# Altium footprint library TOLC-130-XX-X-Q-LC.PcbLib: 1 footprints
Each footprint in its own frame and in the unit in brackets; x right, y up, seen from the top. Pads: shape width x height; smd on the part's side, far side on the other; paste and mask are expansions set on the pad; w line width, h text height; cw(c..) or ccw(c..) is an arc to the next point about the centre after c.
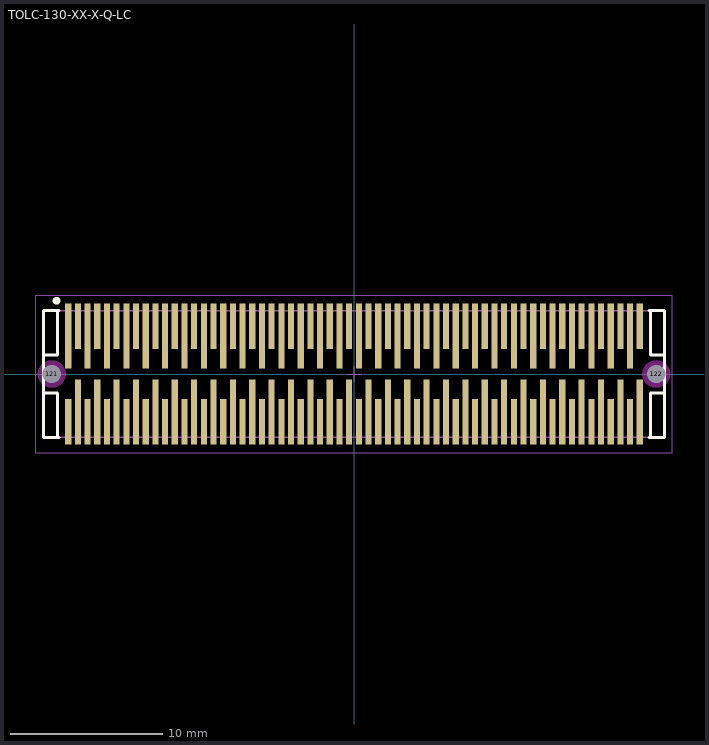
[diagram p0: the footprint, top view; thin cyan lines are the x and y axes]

## TOLC-130-XX-X-Q-LC [mm] "1.27mm pitch, 120 pin, terminal strip; 4 rows, w/locking clips, SMT"
height 5.59
pads (122):
  rect 0.4x4.25 smd mask+0: 1(-18.732,2.5) 4(-18.098,-2.5) 5(-17.462,2.5) 8(-16.828,-2.5) 9(-16.192,2.5) 12(-15.557,-2.5) 13(-14.922,2.5) 16(-14.287,-2.5) 17(-13.652,2.5) 20(-13.018,-2.5) 21(-12.383,2.5) 24(-11.747,-2.5) 25(-11.112,2.5) 28(-10.477,-2.5) 29(-9.842,2.5) 32(-9.207,-2.5) 33(-8.572,2.5) 36(-7.938,-2.5) 37(-7.302,2.5) 40(-6.667,-2.5) 41(-6.032,2.5) 44(-5.397,-2.5) 45(-4.763,2.5) 48(-4.127,-2.5) 49(-3.492,2.5) 52(-2.857,-2.5) 53(-2.222,2.5) 56(-1.587,-2.5) 57(-0.953,2.5) 60(-0.318,-2.5) 61(0.318,2.5) 64(0.953,-2.5) 65(1.587,2.5) 68(2.222,-2.5) 69(2.857,2.5) 72(3.492,-2.5) 73(4.127,2.5) 76(4.763,-2.5) 77(5.397,2.5) 80(6.032,-2.5) 81(6.667,2.5) 84(7.302,-2.5) 85(7.938,2.5) 88(8.572,-2.5) 89(9.207,2.5) 92(9.842,-2.5) 93(10.477,2.5) 96(11.112,-2.5) 97(11.747,2.5) 100(12.383,-2.5) 101(13.018,2.5) 104(13.652,-2.5) 105(14.287,2.5) 108(14.922,-2.5) 109(15.557,2.5) 112(16.192,-2.5) 113(16.828,2.5) 116(17.462,-2.5) 117(18.098,2.5) 120(18.732,-2.5)
  rect 0.4x3 smd mask+0: 2(-18.732,-3.135) 3(-18.098,3.135) 6(-17.462,-3.135) 7(-16.828,3.135) 10(-16.192,-3.135) 11(-15.557,3.135) 14(-14.922,-3.135) 15(-14.287,3.135) 18(-13.652,-3.135) 19(-13.018,3.135) 22(-12.383,-3.135) 23(-11.747,3.135) 26(-11.112,-3.135) 27(-10.477,3.135) 30(-9.842,-3.135) 31(-9.207,3.135) 34(-8.572,-3.135) 35(-7.938,3.135) 38(-7.302,-3.135) 39(-6.667,3.135) 42(-6.032,-3.135) 43(-5.397,3.135) 46(-4.763,-3.135) 47(-4.127,3.135) 50(-3.492,-3.135) 51(-2.857,3.135) 54(-2.222,-3.135) 55(-1.587,3.135) 58(-0.953,-3.135) 59(-0.318,3.135) 62(0.318,-3.135) 63(0.953,3.135) 66(1.587,-3.135) 67(2.222,3.135) 70(2.857,-3.135) 71(3.492,3.135) 74(4.127,-3.135) 75(4.763,3.135) 78(5.397,-3.135) 79(6.032,3.135) 82(6.667,-3.135) 83(7.302,3.135) 86(7.938,-3.135) 87(8.572,3.135) 90(9.207,-3.135) 91(9.842,3.135) 94(10.477,-3.135) 95(11.112,3.135) 98(11.747,-3.135) 99(12.383,3.135) 102(13.018,-3.135) 103(13.652,3.135) 106(14.287,-3.135) 107(14.922,3.135) 110(15.557,-3.135) 111(16.192,3.135) 114(16.828,-3.135) 115(17.462,3.135) 118(18.098,-3.135) 119(18.732,3.135)
  round 1 hole 1.2 unplated mask+0: 121(-19.812,0) 122(19.812,0)
Top Overlay:
  circle w0.25: c-19.5,4.8 r0.125
  lines w0.2: -20.35,-1.25 -19.45,-1.25 -19.45,-4.15 ; -20.35,1.25 -19.45,1.25 -19.45,4.15 ; -19.35,-4.15 -20.35,-4.15 -20.35,4.15 -19.35,4.15 ; 19.35,-4.15 20.35,-4.15 20.35,4.15 19.35,4.15 ; 19.45,-4.15 19.45,-1.25 20.35,-1.25 ; 19.45,4.15 19.45,1.25 20.35,1.25
Keep-Out Layer:
  pour cut-out: 20.72,0 20.689,0.235 20.598,0.454 20.454,0.642 20.266,0.786 20.047,0.877 19.812,0.908 19.577,0.877 19.358,0.786 19.17,0.642 19.026,0.454 18.935,0.235 18.904,0 18.935,-0.235 19.026,-0.454 19.17,-0.642 19.358,-0.786 19.577,-0.877 19.812,-0.908 20.047,-0.877 20.266,-0.786 20.454,-0.642 20.598,-0.454 20.689,-0.235
  pour cut-out: -18.904,0 -18.935,0.235 -19.026,0.454 -19.17,0.642 -19.358,0.786 -19.577,0.877 -19.812,0.908 -20.047,0.877 -20.266,0.786 -20.454,0.642 -20.598,0.454 -20.689,0.235 -20.72,0 -20.689,-0.235 -20.598,-0.454 -20.454,-0.642 -20.266,-0.786 -20.047,-0.877 -19.812,-0.908 -19.577,-0.877 -19.358,-0.786 -19.17,-0.642 -19.026,-0.454 -18.935,-0.235
Mechanical 12:
  lines w0.001: -20.35,-4.15 20.35,-4.15 20.35,4.15 -20.35,4.15 -20.35,-4.15 ; -20.35,-1.25 -20.35,1.25 -19.45,1.25 -19.45,4.15 19.45,4.15 19.45,1.25 20.35,1.25 20.35,-1.25 19.45,-1.25 19.45,-4.15 -19.45,-4.15 -19.45,-1.25 -20.35,-1.25
Mechanical 13:
  circle w0.1: c-18.749,3.265 r0.127
  lines w0.1: -20.35,-4.15 20.35,-4.15 20.35,4.15 -20.35,4.15 -20.35,-4.15 ; -20.35,-1.25 -20.35,1.25 -19.45,1.25 -19.45,4.15 19.45,4.15 19.45,1.25 20.35,1.25 20.35,-1.25 19.45,-1.25 19.45,-4.15 -19.45,-4.15 -19.45,-1.25 -20.35,-1.25
  text ".Designator" at 0,-0.127 h1.52
Mechanical 15:
  lines w0.05: -0.5,0 0.5,0 ; 0,-0.5 0,0.5 ; -20.85,-5.15 -20.85,5.15 20.85,5.15 20.85,-5.15 -20.85,-5.15
Mechanical 16:
  circle w0.001: c-18.749,3.265 r0.127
